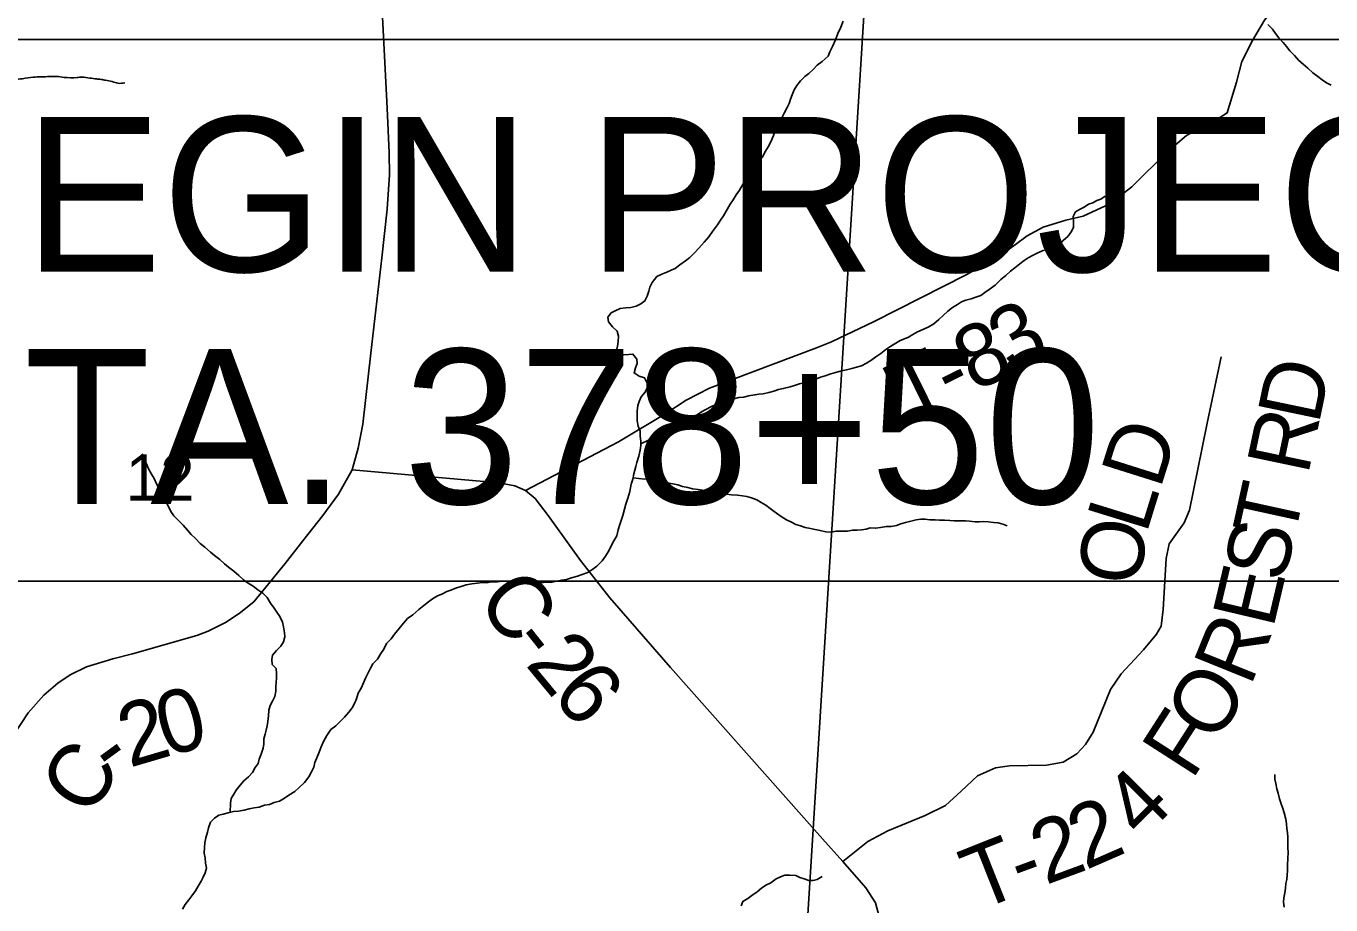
# Model space of a CAD drawing. Extents: x -20.2 to 34, y 0 to 22.
# Drawn here: x 6.216 to 7.395, y 18.094 to 18.889 of the extents above; entities that cross this region are included whole.
import ezdxf

# ---------------------------------------------------------------- set-up
doc = ezdxf.new("R2010")
doc.units = 0
for name, color, linetype in [('GM_X_County_Road', 7, 'Continuous'), ('GM_X_County_Road_Text', 7, 'Continuous'), ('GM_X_Minor_River', 7, 'Continuous'), ('GM_X_Section', 7, 'Continuous'), ('GM_X_Section_Text', 7, 'Continuous'), ('GM_X_Township_Road', 7, 'Continuous'), ('GM_X_Township_Road_Text', 7, 'Continuous'), ('SH_Masking', 7, 'Continuous'), ('SH_Text', 7, 'Continuous')]:
    doc.layers.add(name, color=color, linetype=linetype)

msp = doc.modelspace()

# ---------------------------------------------------------------- linework, layer by layer
at = {"layer": 'GM_X_County_Road'}
for points in [[(6.5106, 18.4875), (6.516, 18.5069), (6.5202, 18.5288), (6.5273, 18.5929), (6.5375, 18.6791), (6.5423, 18.7231), (6.5443, 18.7542), (6.544, 18.774), (6.5423, 18.8144), (6.5378, 18.9028), (6.5359, 18.9404), (6.5334, 18.9922), (6.5331, 18.9992), (6.533, 19.0001)], [(6.1963, 18.235), (6.2178, 18.2676), (6.2318, 18.2835), (6.2444, 18.2944), (6.2556, 18.302), (6.2704, 18.3092), (6.2942, 18.3165), (6.3119, 18.321), (6.3701, 18.3375), (6.3805, 18.3414), (6.3961, 18.3493), (6.4085, 18.3574), (6.4216, 18.368), (6.4499, 18.4028), (6.4661, 18.4232), (6.4841, 18.4462), (6.4983, 18.4655), (6.5106, 18.4875)], [(6.5106, 18.4875), (6.6432, 18.4755), (6.6576, 18.4728), (6.6674, 18.4687), (6.6761, 18.4613), (6.6876, 18.446), (6.7171, 18.4055), (6.7436, 18.3716), (6.7983, 18.3087), (6.9358, 18.1535), (6.9541, 18.133), (6.9749, 18.1094), (6.9837, 18.0958), (6.9916, 18.0664)]]:
    msp.add_lwpolyline(points, dxfattribs=at)
at = {"layer": 'GM_X_Minor_River'}
for points in [[(6.9545, 18.8932), (6.9522, 18.8878), (6.9497, 18.8821), (6.9474, 18.8764), (6.9449, 18.8703), (6.9423, 18.8653), (6.9408, 18.8615), (6.9355, 18.8568), (6.931, 18.8534), (6.9273, 18.8495), (6.9235, 18.8457), (6.9197, 18.843), (6.916, 18.8391), (6.9126, 18.8349), (6.91, 18.8311), (6.9082, 18.8265), (6.9067, 18.8227), (6.9056, 18.8188), (6.9038, 18.815), (6.9015, 18.8104), (6.8986, 18.8051), (6.896, 18.7993), (6.8937, 18.7955), (6.8915, 18.7898), (6.8889, 18.7841), (6.8867, 18.7795), (6.8841, 18.7756), (6.8815, 18.7703), (6.8781, 18.7664), (6.8744, 18.7618), (6.871, 18.7561), (6.8669, 18.7515), (6.864, 18.7461), (6.8606, 18.7404), (6.8576, 18.7362), (6.855, 18.7316), (6.8524, 18.7277), (6.8487, 18.7212), (6.8461, 18.717), (6.8435, 18.7132), (6.8409, 18.709), (6.8364, 18.7028), (6.833, 18.6982), (6.8289, 18.6932), (6.824, 18.6879), (6.8203, 18.684), (6.8158, 18.6794), (6.812, 18.6763), (6.8067, 18.6728), (6.8026, 18.6694), (6.7988, 18.6678), (6.7951, 18.6662), (6.7905, 18.6643), (6.786, 18.6623), (6.7819, 18.6569), (6.7796, 18.6527), (6.7786, 18.6489), (6.7771, 18.6443), (6.7752, 18.6401), (6.7715, 18.6374), (6.7673, 18.6355), (6.7624, 18.6343), (6.7579, 18.6338), (6.7529, 18.6334), (6.7484, 18.6311), (6.7446, 18.6295), (6.7416, 18.6253), (6.7424, 18.6211), (6.7459, 18.6166), (6.7501, 18.6128), (6.7513, 18.6083), (6.751, 18.6033), (6.7503, 18.5992), (6.7496, 18.5954), (6.7519, 18.5916), (6.7561, 18.5913), (6.7606, 18.5917), (6.7644, 18.5921), (6.7679, 18.5876), (6.7683, 18.5834)], [(7.3383, 18.89), (7.3425, 18.8859), (7.3452, 18.8821), (7.3483, 18.878), (7.3521, 18.8739), (7.3552, 18.8701), (7.3583, 18.8663), (7.3625, 18.8622), (7.3664, 18.8577), (7.3702, 18.8543), (7.3744, 18.8506), (7.379, 18.8465), (7.3836, 18.8431), (7.3874, 18.8401), (7.3913, 18.8375), (7.3955, 18.8353)], [(7.1913, 18.735), (7.1875, 18.7323), (7.1838, 18.7308), (7.18, 18.7288), (7.1762, 18.7276), (7.1724, 18.7249), (7.1687, 18.723), (7.1645, 18.7206), (7.1623, 18.7164), (7.1627, 18.7115), (7.1628, 18.7066), (7.1605, 18.7027), (7.1576, 18.6985), (7.1534, 18.6947), (7.1489, 18.6908), (7.1444, 18.6885), (7.1402, 18.6869), (7.1353, 18.6857), (7.1304, 18.6837), (7.1263, 18.6814), (7.1217, 18.6791), (7.118, 18.6767), (7.1142, 18.6736), (7.1097, 18.6702), (7.1056, 18.6671), (7.1014, 18.6632), (7.0969, 18.6594), (7.0917, 18.6544), (7.0864, 18.6505), (7.0826, 18.6478), (7.0789, 18.6451), (7.0743, 18.6435), (7.0702, 18.6419), (7.0652, 18.6407), (7.0615, 18.6392), (7.0577, 18.6368), (7.0532, 18.6341), (7.049, 18.631), (7.0449, 18.6268), (7.0408, 18.6233), (7.0363, 18.6195), (7.0314, 18.6164), (7.0265, 18.6144), (7.0216, 18.6121), (7.0174, 18.6097), (7.0136, 18.6074), (7.0099, 18.6058), (7.0061, 18.6043), (7.0019, 18.6019), (6.9974, 18.5992), (6.9929, 18.5961), (6.9884, 18.5927), (6.9839, 18.5896), (6.9793, 18.5861), (6.9756, 18.5837), (6.971, 18.5814), (6.9665, 18.5802), (6.9623, 18.579), (6.9574, 18.5778), (6.9529, 18.577), (6.9476, 18.5754), (6.9434, 18.5742), (6.9381, 18.5723), (6.934, 18.5711), (6.9287, 18.5691), (6.9249, 18.5679), (6.92, 18.5663), (6.9151, 18.5651), (6.9105, 18.5636), (6.9064, 18.5624), (6.9003, 18.5608), (6.8961, 18.56), (6.8916, 18.5584), (6.8871, 18.5572), (6.8821, 18.556), (6.8783, 18.5559), (6.8746, 18.5551), (6.8689, 18.5543), (6.8647, 18.5531), (6.8602, 18.5527), (6.8556, 18.5515), (6.8503, 18.5503), (6.8465, 18.5498), (6.8424, 18.5486), (6.8386, 18.5463), (6.8348, 18.5444), (6.8303, 18.542), (6.8265, 18.5397), (6.8216, 18.5366), (6.8175, 18.5346), (6.8133, 18.5323), (6.8096, 18.53), (6.8058, 18.5277), (6.802, 18.5261), (6.7979, 18.523), (6.7934, 18.5207), (6.7896, 18.5187), (6.7854, 18.5175), (6.7715, 18.5109)], [(6.7683, 18.5834), (6.7668, 18.5796), (6.7654, 18.575), (6.77, 18.572), (6.7749, 18.5706), (6.7773, 18.5657), (6.7773, 18.5611), (6.7751, 18.5573), (6.7717, 18.5535), (6.7699, 18.5492), (6.7688, 18.5454), (6.7681, 18.5405), (6.7681, 18.5359), (6.7682, 18.5317), (6.769, 18.5268), (6.7709, 18.5223), (6.771, 18.5177), (6.7714, 18.5132), (6.7715, 18.5094), (6.7708, 18.5052), (6.7697, 18.4998), (6.7679, 18.4941), (6.7671, 18.4903), (6.7653, 18.4838), (6.7642, 18.4789), (6.7628, 18.4743), (6.7617, 18.4678), (6.7599, 18.4617), (6.7581, 18.4564), (6.7566, 18.4518), (6.7551, 18.4461), (6.7533, 18.4407), (6.7522, 18.4369), (6.7511, 18.4331), (6.7497, 18.4278), (6.7463, 18.4217), (6.7441, 18.4171), (6.7419, 18.4132), (6.7396, 18.4094), (6.7366, 18.4052), (6.7318, 18.4002), (6.728, 18.3975), (6.7235, 18.3944), (6.7186, 18.3928), (6.7144, 18.3912), (6.7087, 18.3896), (6.7042, 18.3881), (6.7, 18.3876), (6.694, 18.3864), (6.6898, 18.3856), (6.686, 18.3859), (6.6811, 18.3851), (6.6769, 18.3854), (6.6731, 18.3854), (6.6685, 18.3861), (6.6644, 18.3864), (6.6606, 18.3868), (6.6549, 18.3863), (6.6507, 18.3863), (6.6461, 18.3866), (6.642, 18.3861), (6.6363, 18.3861), (6.6321, 18.3853), (6.6283, 18.3856), (6.6238, 18.3848), (6.6188, 18.3843), (6.6135, 18.3835), (6.609, 18.3819), (6.6048, 18.3807), (6.5999, 18.3784), (6.5961, 18.3772), (6.5916, 18.3749), (6.5878, 18.3733), (6.5833, 18.3706), (6.5795, 18.3679), (6.5754, 18.3648), (6.5709, 18.3609), (6.5653, 18.3563), (6.5607, 18.3528), (6.557, 18.3486), (6.5529, 18.344), (6.5488, 18.3386), (6.5458, 18.3344), (6.5417, 18.3302), (6.5391, 18.3252), (6.5364, 18.3214), (6.5335, 18.316), (6.5293, 18.3118), (6.5271, 18.3079), (6.5245, 18.3026), (6.5227, 18.2988), (6.5208, 18.2946), (6.5186, 18.29), (6.516, 18.2854), (6.5145, 18.2804), (6.5131, 18.2766), (6.5105, 18.272), (6.5075, 18.2682), (6.5037, 18.2636), (6.5, 18.2601), (6.4958, 18.2559)], [(6.3206, 18.5018), (6.3226, 18.4965), (6.3245, 18.4927), (6.3265, 18.4882), (6.3292, 18.4833), (6.3315, 18.4795), (6.3338, 18.4746), (6.3362, 18.4705), (6.3381, 18.4663), (6.3408, 18.4622), (6.3428, 18.4576), (6.3447, 18.4535), (6.3466, 18.4497), (6.3493, 18.4459), (6.3532, 18.4418), (6.3578, 18.4373), (6.3617, 18.4328), (6.3651, 18.429), (6.369, 18.4253), (6.3732, 18.4208), (6.3774, 18.4174), (6.3824, 18.4129), (6.3862, 18.4099), (6.3908, 18.4062), (6.395, 18.4024), (6.3989, 18.3994), (6.4035, 18.3957), (6.4081, 18.3919), (6.4123, 18.3878), (6.4165, 18.3848), (6.4211, 18.3822), (6.4253, 18.3789), (6.4299, 18.3759), (6.4337, 18.3718), (6.4368, 18.3668), (6.4399, 18.3623), (6.4426, 18.3586), (6.4453, 18.3548), (6.4477, 18.3495), (6.4485, 18.3453), (6.4493, 18.34), (6.4497, 18.3362), (6.4486, 18.3317), (6.446, 18.3278), (6.4423, 18.324), (6.4385, 18.3198), (6.4378, 18.3159), (6.4382, 18.3114), (6.4417, 18.3076), (6.4421, 18.3031), (6.4422, 18.2993), (6.4419, 18.2951), (6.4415, 18.2913), (6.4416, 18.2871), (6.4405, 18.2825), (6.4386, 18.278), (6.4364, 18.2741), (6.4353, 18.2699), (6.435, 18.265), (6.4343, 18.2597), (6.4336, 18.2559), (6.4329, 18.252), (6.4318, 18.2482), (6.4307, 18.244), (6.4307, 18.2395), (6.43, 18.2357), (6.4282, 18.2303), (6.4264, 18.2257), (6.4256, 18.2219), (6.423, 18.2181), (6.4204, 18.2135), (6.4167, 18.2097), (6.4125, 18.2062), (6.4092, 18.2023), (6.4058, 18.1977), (6.4036, 18.1939), (6.4013, 18.1901), (6.4006, 18.1859), (6.4004, 18.1776)], [(7.1026, 18.4368), (7.0988, 18.4382), (7.0946, 18.4393), (7.0904, 18.4397), (7.0858, 18.4404), (7.0813, 18.4407), (7.0775, 18.4403), (7.0737, 18.4402), (7.0687, 18.4409), (7.0649, 18.4412), (7.0593, 18.4412), (7.0547, 18.4411), (7.0509, 18.4414), (7.046, 18.4418), (7.0414, 18.4417), (7.0376, 18.442), (7.0327, 18.442), (7.0285, 18.4427), (7.0247, 18.4426), (7.0205, 18.4422), (7.0156, 18.441), (7.0107, 18.4398), (7.0065, 18.4386), (7.0027, 18.437), (6.9978, 18.4362), (6.9936, 18.4362), (6.9883, 18.4353), (6.9838, 18.4345), (6.9789, 18.4348), (6.9751, 18.4336), (6.9709, 18.4332), (6.9671, 18.4328), (6.9629, 18.4327), (6.9584, 18.4319), (6.9527, 18.4318), (6.9481, 18.4318), (6.944, 18.431), (6.9387, 18.4313), (6.9337, 18.4324), (6.9291, 18.4334), (6.925, 18.4342), (6.92, 18.4352), (6.9158, 18.4367), (6.9116, 18.4378), (6.9078, 18.44), (6.9032, 18.4422), (6.8983, 18.4452), (6.8921, 18.4497), (6.8883, 18.4523), (6.8845, 18.4553), (6.8803, 18.4579), (6.8764, 18.4601), (6.8715, 18.462), (6.8673, 18.4631), (6.8635, 18.4638), (6.8589, 18.4645), (6.8536, 18.4648), (6.849, 18.4655), (6.8445, 18.4662), (6.8403, 18.4665), (6.8361, 18.4672), (6.8316, 18.4679), (6.827, 18.469), (6.8232, 18.4697), (6.8182, 18.4701), (6.8141, 18.4715), (6.8091, 18.4722), (6.8049, 18.4737), (6.8003, 18.4748), (6.7954, 18.4755), (6.7908, 18.4769), (6.787, 18.4773), (6.7832, 18.4784), (6.7794, 18.4791), (6.7749, 18.479), (6.7645, 18.4801)], [(6.4958, 18.2559), (6.4913, 18.2524), (6.4876, 18.247), (6.4846, 18.2417), (6.4824, 18.2367), (6.4806, 18.2321), (6.4787, 18.2268), (6.4769, 18.2226), (6.4758, 18.2184), (6.4739, 18.2142), (6.4713, 18.2096), (6.4676, 18.2046), (6.4627, 18.2), (6.4586, 18.1965), (6.4533, 18.193), (6.4495, 18.1903), (6.445, 18.1876), (6.4401, 18.1864), (6.4359, 18.1848), (6.4314, 18.184), (6.4265, 18.1824), (6.4219, 18.1816), (6.4174, 18.1808), (6.4129, 18.1796), (6.4079, 18.1788), (6.4034, 18.1783), (6.3985, 18.1771), (6.3939, 18.1759), (6.3901, 18.1751), (6.386, 18.1724), (6.3826, 18.1686), (6.3808, 18.1636), (6.3797, 18.1598), (6.3782, 18.1545), (6.3775, 18.1499), (6.3772, 18.1457), (6.3769, 18.1408), (6.3777, 18.1366), (6.3781, 18.1317), (6.3789, 18.1271), (6.3778, 18.1229), (6.376, 18.1191), (6.3741, 18.1153), (6.3712, 18.1107), (6.3689, 18.1065), (6.3656, 18.1022), (6.3629, 18.0984), (6.3596, 18.0942), (6.3573, 18.09)], [(7.3448, 18.2118), (7.3448, 18.2076), (7.3456, 18.2038), (7.3464, 18.1989), (7.3476, 18.1948), (7.3488, 18.1898), (7.3504, 18.1853), (7.352, 18.1811), (7.3531, 18.1773), (7.3547, 18.1713), (7.3552, 18.1671), (7.3556, 18.1629), (7.356, 18.1591), (7.3564, 18.155), (7.3565, 18.15), (7.3565, 18.1462), (7.3566, 18.1409), (7.3563, 18.1363), (7.356, 18.1295), (7.356, 18.1249), (7.3557, 18.1208), (7.3554, 18.117), (7.3547, 18.1131), (7.3543, 18.109), (7.3536, 18.1048), (7.3529, 18.1002), (7.3526, 18.0964), (7.353, 18.0918)], [(6.9355, 18.1197), (6.931, 18.1169), (6.9272, 18.1161), (6.9234, 18.1161), (6.9192, 18.1176), (6.9154, 18.1186), (6.9116, 18.1205), (6.9063, 18.1208), (6.9017, 18.1208), (6.8979, 18.1192), (6.8938, 18.1176), (6.8889, 18.1138), (6.8844, 18.1118), (6.8806, 18.1091), (6.8768, 18.1056), (6.8719, 18.1025), (6.8682, 18.0998), (6.8636, 18.0971), (6.8622, 18.0929)]]:
    msp.add_lwpolyline(points, dxfattribs=at)
msp.add_spline([(6.3051, 18.8373), (6.299, 18.837), (6.2937, 18.8385), (6.2877, 18.8397), (6.2835, 18.8405), (6.2793, 18.8409), (6.2733, 18.8417), (6.2661, 18.8425), (6.2619, 18.8422), (6.2501, 18.8423), (6.2433, 18.8431), (6.2372, 18.8431), (6.2293, 18.8428), (6.2221, 18.8425), (6.2126, 18.8411), (6.2053, 18.8407), (6.1974, 18.8408), (6.1924, 18.8405), (6.1852, 18.8405), (6.1784, 18.8402), (6.1742, 18.8398), (6.1651, 18.8388), (6.1567, 18.8369), (6.1522, 18.8355), (6.1449, 18.8325), (6.1396, 18.8302), (6.1347, 18.8265), (6.1274, 18.8212), (6.1224, 18.8175), (6.1179, 18.8141), (6.1121, 18.8081), (6.1072, 18.8043), (6.1022, 18.8017), (6.0958, 18.7994), (6.0912, 18.7976), (6.0821, 18.7946), (6.0779, 18.7935), (6.0729, 18.7932), (6.0669, 18.7925), (6.0627, 18.7917), (6.0581, 18.7918), (6.0524, 18.7922), (6.046, 18.7941), (6.0399, 18.7968), (6.0354, 18.798), (6.0312, 18.7988), (6.0248, 18.8), (6.0146, 18.8016), (6.0081, 18.8032), (6.0028, 18.8051), (5.9979, 18.8067), (5.9907, 18.8094), (5.9843, 18.8125), (5.9797, 18.8148), (5.9744, 18.8163), (5.9638, 18.8164), (5.9555, 18.8161), (5.9498, 18.8162), (5.9452, 18.8166), (5.9388, 18.8181), (5.9308, 18.819), (5.9251, 18.8201), (5.921, 18.8206), (5.9168, 18.8217), (5.9119, 18.8229), (5.9073, 18.8237), (5.9009, 18.8249), (5.8952, 18.8253), (5.8895, 18.8254), (5.8853, 18.8231), (5.8754, 18.8179), (5.8709, 18.8168), (5.8625, 18.8153), (5.8568, 18.8127), (5.8522, 18.8116), (5.8473, 18.8097), (5.8401, 18.8079), (5.834, 18.8064), (5.8252, 18.8065), (5.8169, 18.8073), (5.8108, 18.8081), (5.8067, 18.8097), (5.793, 18.8136), (5.7874, 18.8163), (5.7805, 18.8175), (5.7749, 18.8187), (5.7703, 18.8191), (5.765, 18.8195), (5.7605, 18.8199), (5.7551, 18.8207), (5.7502, 18.8211), (5.7438, 18.8227), (5.7385, 18.8239), (5.7343, 18.8258), (5.7286, 18.8293), (5.7302, 18.8357), (5.7314, 18.8418)], degree=3, dxfattribs=at)
at = {"layer": 'GM_X_Section'}
for points in [[(5.9021, 19.0275), (5.9253, 19.026), (6.9777, 18.9706), (6.915, 17.9639), (5.8423, 18.0007)], [(6.9777, 18.9706), (8.0404, 18.9117), (7.9819, 17.9077), (6.915, 17.9639)]]:
    msp.add_lwpolyline(points, close=True, dxfattribs=at)
at = {"layer": 'GM_X_Township_Road'}
for points in [[(7.2548, 18.7814), (7.2648, 18.7897), (7.2783, 18.7972), (7.2921, 18.8041), (7.3017, 18.8102), (7.3101, 18.8379), (7.3147, 18.8567), (7.3246, 18.8757), (7.3353, 18.894), (7.3527, 18.9157), (7.3694, 18.9315), (7.3802, 18.9384), (7.3966, 18.9427), (7.3996, 18.9426)], [(7.1674, 18.716), (7.1713, 18.7169), (7.1955, 18.7279), (7.2154, 18.7432), (7.2479, 18.7757), (7.2548, 18.7814)], [(6.6674, 18.4687), (6.7512, 18.5128), (6.7942, 18.5384), (6.8125, 18.5503), (6.8335, 18.5613), (6.9303, 18.5977), (6.9439, 18.6031), (6.9825, 18.6215), (7.0656, 18.6638), (7.0969, 18.6814), (7.1102, 18.6913), (7.1207, 18.6991), (7.1351, 18.7068), (7.1557, 18.7132), (7.1674, 18.716)], [(6.9541, 18.133), (6.9768, 18.1513), (6.9949, 18.1609), (7.0287, 18.1746), (7.047, 18.1838), (7.0612, 18.1967), (7.0759, 18.2106), (7.0921, 18.2177), (7.1047, 18.2197), (7.1383, 18.2204), (7.1534, 18.2229), (7.1658, 18.2305), (7.1736, 18.2389), (7.1804, 18.2501), (7.196, 18.2886), (7.2058, 18.303), (7.2259, 18.3247), (7.2378, 18.3387), (7.242, 18.346), (7.2436, 18.3611), (7.2465, 18.4073), (7.2492, 18.4205), (7.2628, 18.4394), (7.2674, 18.451), (7.2751, 18.4881), (7.2834, 18.5297), (7.2962, 18.5895)]]:
    msp.add_lwpolyline(points, dxfattribs=at)
at = {"layer": 'SH_Masking'}
msp.add_lwpolyline([(6.0189, 18.3866), (7.7544, 18.3866), (7.7544, 18.8766), (6.0189, 18.8766)], close=True, dxfattribs=at)
at = {"layer": 'SH_Text'}
msp.add_lwpolyline([(6.0189, 18.3866), (6.0189, 18.8766), (7.7544, 18.8766), (7.7544, 18.3866)], close=True, dxfattribs=at)

# ---------------------------------------------------------------- texts
at = {"layer": 'GM_X_County_Road_Text'}
for s, rotation, p in [('C', 307.0791, (6.6219, 18.3691)), ('-', 308.382, (6.6509, 18.3308)), ('2', 309.6909, (6.6663, 18.3114)), ('6', 310.9857, (6.6895, 18.2834)), ('0', 15.3793, (6.3424, 18.2276)), ('2', 16.4186, (6.3091, 18.2178)), ('C', 55.9484, (6.2723, 18.1714)), ('-', 36.0549, (6.2948, 18.2063))]:
    msp.add_text(s, height=0.0568, rotation=rotation, dxfattribs=at).set_placement(p)
at = {"layer": 'GM_X_Section_Text'}
msp.add_text('12', height=0.04186, rotation=0, dxfattribs=at).set_placement((6.3058, 18.4596))
at = {"layer": 'GM_X_Township_Road_Text'}
for s, rotation, p in [('3', 29.099, (7.1065, 18.5742)), ('8', 27.0698, (7.0734, 18.5572)), ('T', 26.3791, (7.0138, 18.5276)), ('-', 26.5237, (7.052, 18.5465)), ('D', 78.2297, (7.3843, 18.5274)), ('R', 78.1259, (7.3746, 18.4817)), ('D', 72.4602, (7.2409, 18.4689)), ('T', 77.6416, (7.3618, 18.4225)), ('L', 72.8472, (7.2284, 18.4284)), ('O', 82.6983, (7.2226, 18.3813)), ('S', 76.7151, (7.3527, 18.3842)), ('E', 76.7127, (7.343, 18.3429)), ('R', 68.0007, (7.3226, 18.2906)), ('O', 57.4772, (7.2905, 18.2383)), ('F', 57.3036, (7.2697, 18.2059)), ('4', 45.0925, (7.2247, 18.1522)), ('2', 23.5829, (7.1735, 18.1251)), ('2', 20.2818, (7.1374, 18.1117)), ('T', 21.6948, (7.0763, 18.088)), ('-', 20.1805, (7.1154, 18.1036))]:
    msp.add_text(s, height=0.0568, rotation=rotation, dxfattribs=at).set_placement(p)
at = {"layer": 'SH_Text'}
for s, p in [('BEGIN PROJECT', (6.0889, 18.6666)), ('STA. 378+50', (6.0889, 18.4566))]:
    msp.add_text(s, height=0.14, dxfattribs=at).set_placement(p)

doc.saveas('drawing.dxf')
